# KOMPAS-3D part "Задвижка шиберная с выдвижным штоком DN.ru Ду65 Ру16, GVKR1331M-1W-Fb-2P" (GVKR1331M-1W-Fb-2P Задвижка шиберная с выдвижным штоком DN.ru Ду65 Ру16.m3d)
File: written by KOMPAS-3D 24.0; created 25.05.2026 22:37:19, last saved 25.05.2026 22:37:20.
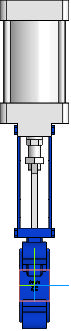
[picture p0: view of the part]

Document properties: Автор: R2D2; Полное имя файла: E:\Работа\Зайцев\GVKR1331M-1W-Fb-2P Задвижка шиберная с выдвижным штоком DN.ru Ду50-300 Ру16-10-6 с пневмоприводом\исходные материалы\DN65\DN65\GVKR1331M-1W-Fb-2P Задвижка шиберная с выдвижным штоком DN.ru Ду65 Ру16.m3d

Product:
- Part/product: Задвижка шиберная с выдвижным штоком DN.ru Ду65 Ру16  | designation GVKR1331M-1W-Fb-2P
    Масса: 9.5
    Раздел спецификации: Прочие изделия
    Примечание: D040-08792

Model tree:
1. Операция без истории:1

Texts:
  GVKR1331M-1W-Fb-2P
